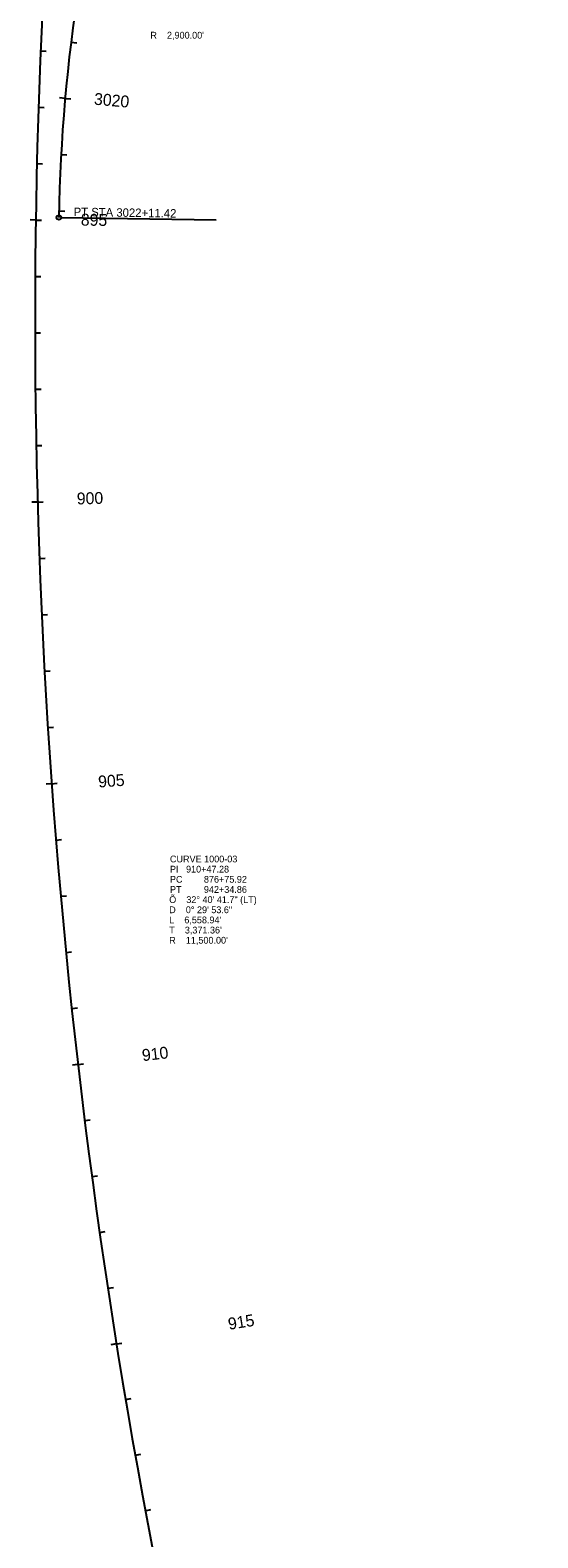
# Model space of a CAD drawing. Extents: x 2819977 to 2827606, y 113942 to 150283.
# Drawn here: x 2820825 to 2821726, y 127660 to 130332 of the extents above; entities that cross this region are included whole.
import ezdxf

# ---------------------------------------------------------------- set-up
doc = ezdxf.new("R2010")
doc.units = 0
for name, color, linetype in [('Level 63', 7, 'Continuous'), ('Roadway-Safety', 7, 'Continuous'), ('Roadway-Walls', 7, 'Continuous'), ('Utility-Power', 7, 'Continuous')]:
    doc.layers.add(name, color=color, linetype=linetype)

msp = doc.modelspace()

# ---------------------------------------------------------------- linework, layer by layer
at = {"layer": 'Level 63'}
msp.add_circle((2820876.1, 130000.1), 4, dxfattribs=at)
at = {"layer": 'Roadway-Safety'}
msp.add_line((2820880.1, 130000.1), (2821154.8, 129995.8), dxfattribs=at)
at = {"layer": 'Utility-Power'}
for p, q in [((2820843.5, 130295.5), (2820853.5, 130295.1)), ((2820897.7, 130310.7), (2820907.6, 130309.4)), ((2820887.1, 130211.2), (2820877.2, 130212.1)), ((2820887.1, 130211.2), (2820897.1, 130210.3)), ((2820839.8, 130195.6), (2820849.8, 130195.3)), ((2820880, 130111.5), (2820890, 130110.9)), ((2820837, 130095.6), (2820847, 130095.4)), ((2820835, 129995.6), (2820825, 129995.8)), ((2820835, 129995.6), (2820845, 129995.5)), ((2820876.3, 130011.6), (2820886.3, 130011.4)), ((2820833.9, 129895.7), (2820843.9, 129895.6)), ((2820833.7, 129795.7), (2820843.7, 129795.7)), ((2820834.4, 129695.7), (2820844.4, 129695.8)), ((2820835.9, 129595.7), (2820845.9, 129595.9)), ((2820838.3, 129495.7), (2820828.3, 129495.4)), ((2820838.3, 129495.7), (2820848.3, 129496)), ((2820841.5, 129395.8), (2820851.5, 129396.1)), ((2820845.7, 129295.8), (2820855.6, 129296.3)), ((2820850.7, 129196), (2820860.6, 129196.5)), ((2820856.5, 129096.1), (2820866.5, 129096.8)), ((2820863.2, 128996.4), (2820853.3, 128995.6)), ((2820863.2, 128996.4), (2820873.2, 128997.1)), ((2820870.8, 128896.6), (2820880.8, 128897.5)), ((2820879.3, 128797), (2820889.3, 128797.9)), ((2820888.6, 128697.4), (2820898.6, 128698.4)), ((2820898.8, 128598), (2820908.8, 128599)), ((2820909.9, 128498.6), (2820900, 128497.4)), ((2820909.9, 128498.6), (2820919.8, 128499.7)), ((2820921.8, 128399.3), (2820931.7, 128400.5)), ((2820934.6, 128300.1), (2820944.5, 128301.4)), ((2820948.3, 128201.1), (2820958.2, 128202.5)), ((2820962.8, 128102.1), (2820972.7, 128103.6)), ((2820978.1, 128003.3), (2820968.3, 128001.7)), ((2820978.1, 128003.3), (2820988, 128004.9)), ((2820994.4, 127904.6), (2821004.2, 127906.3)), ((2821011.4, 127806.1), (2821021.3, 127807.8)), ((2821029.4, 127707.7), (2821039.2, 127709.6))]:
    msp.add_line(p, q, dxfattribs=at)
for centre, radius, start, end in [((2832333.7, 129820.2), 11500, 170.03806, 202.7163), ((2823775.7, 129954.6), 2900, 162.7159, 179.1005)]:
    msp.add_arc(centre, radius, start, end, dxfattribs=at)

# ---------------------------------------------------------------- texts
at = {"layer": 'Roadway-Safety'}
msp.add_text('PT STA 3022+11.42', height=15, rotation=359.1005, dxfattribs=at).set_placement((2820902.1, 130002.7))
at = {"layer": 'Roadway-Walls'}
for s, p in [("R    2,900.00'", (2821038.4, 130317.2)), ('CURVE 1000-03', (2821073.1, 128856.9)), ('PI   910+47.28', (2821073.1, 128838.9)), ('PC', (2821073.1, 128820.9)), ('876+75.92', (2821133.3, 128820.9)), ('Õ    32%%d 40\' 41.7" (LT)', (2821071.8, 128784.9)), ('PT', (2821073.1, 128802.9)), ('942+34.86', (2821133.3, 128802.9)), ('D    0%%d 29\' 53.6"', (2821071.8, 128766.9)), ("T    3,371.36'", (2821071.8, 128730.9)), ("L    6,558.94'", (2821071.8, 128748.9)), ("R    11,500.00'", (2821071.8, 128712.9))]:
    msp.add_text(s, height=12, dxfattribs=at).set_placement(p)
at = {"layer": 'Utility-Power'}
for s, rotation, p in [(' 3020', 354.9234, (2820929.9, 130200.9)), (' 895', 359.1261, (2820907, 129985.9)), (' 900', 1.6172, (2820900.3, 129491.1)), (' 905', 4.1083, (2820938.7, 128988.9)), (' 910', 6.5994, (2821016.9, 128503.6)), (' 915', 9.0906, (2821170.2, 128027))]:
    msp.add_text(s, height=21, rotation=rotation, dxfattribs=at).set_placement(p)

doc.saveas('drawing.dxf')
